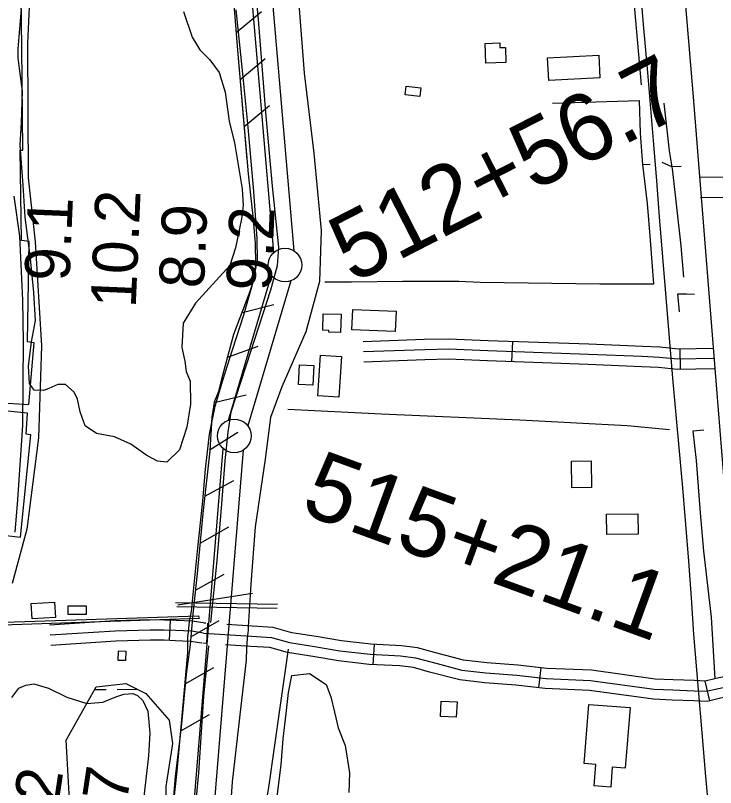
# Model space of a CAD drawing. Extents: x 3715084 to 3753216, y 488173 to 513963.
# Drawn here: x 3735343 to 3736383, y 503889 to 505035 of the extents above; entities that cross this region are included whole.
import ezdxf

# ---------------------------------------------------------------- set-up
doc = ezdxf.new("R2010")
doc.units = 0
for name, color, linetype in [('V-BLDG-OTLN', 7, 'Continuous'), ('V-CHAN-DOCK', 7, 'Continuous'), ('V-FLOD-BASE', 7, 'Continuous'), ('V-LEVE-TOET', 7, 'Continuous'), ('V-RAIL-TRAK', 7, 'Continuous'), ('V-RIVR-EDGE', 7, 'Continuous'), ('V-RIVR-RANG', 7, 'Continuous'), ('V-ROAD-CNTR', 7, 'Continuous'), ('V-RRAP-FSHR', 7, 'Continuous'), ('V-RRAP-RVMT', 7, 'Continuous'), ('V-SITE-VEGE', 7, 'Continuous'), ('V-SURV-IDEN', 7, 'Continuous'), ('V-SURV-LINE', 7, 'Continuous'), ('V-TOPO-SHOR', 7, 'Continuous'), ('V-UTIL-LINE', 7, 'Continuous'), ('V-WETL-SWMP', 7, 'Continuous')]:
    doc.layers.add(name, color=color, linetype=linetype)

msp = doc.modelspace()

# ---------------------------------------------------------------- linework, layer by layer
at = {"layer": 'V-BLDG-OTLN'}
for points in [[(3736040.8, 504993.8), (3736062.7, 504994.4), (3736062.9, 504987.4), (3736071.1, 504987.6), (3736071.7, 504965.5), (3736041.7, 504964.6)], [(3736211.3, 504942.4), (3736135.3, 504938.5), (3736133.6, 504972.2), (3736209.6, 504976)], [(3735923.6, 504930.1), (3735945.5, 504927.5), (3735944, 504914.9), (3735922.1, 504917.5)], [(3735844.1, 504598.6), (3735908.5, 504596), (3735907.3, 504566), (3735842.9, 504568.6)], [(3735800.3, 504592.2), (3735826.7, 504591.6), (3735826, 504564.5), (3735808.7, 504564.9), (3735808.8, 504567.7), (3735799.7, 504568)], [(3735827.3, 504529.1), (3735823.4, 504468.6), (3735792.4, 504470.6), (3735796.3, 504531.1)], [(3735786.3, 504515.5), (3735785, 504486.5), (3735763.5, 504487.5), (3735764.8, 504516.4)], [(3736169.8, 504333.9), (3736169.2, 504373.6), (3736198.5, 504374), (3736199.1, 504334.3)], [(3736221.1, 504294.7), (3736267.9, 504295.4), (3736268.3, 504265.3), (3736221.5, 504264.7)], [(3735366.4, 504162.1), (3735401.1, 504164), (3735402.4, 504141.2), (3735367.6, 504139.3)], [(3735421.1, 504158.9), (3735448.1, 504158.9), (3735448.1, 504146), (3735421.1, 504146)], [(3735506.9, 504091.6), (3735506.5, 504077.4), (3735495.8, 504077.7), (3735496.2, 504091.8)], [(3735975.5, 504017.4), (3735999.3, 504016.1), (3735998, 503993.4), (3735974.3, 503994.7)], [(3736256.2, 504007.6), (3736249.1, 503917.9), (3736229.8, 503919.5), (3736227.4, 503889.6), (3736202.9, 503891.6), (3736205.4, 503923.4), (3736187.8, 503924.8), (3736194.8, 504012.5)]]:
    msp.add_lwpolyline(points, close=True, dxfattribs=at)
at = {"layer": 'V-CHAN-DOCK'}
msp.add_lwpolyline([(3735615.8, 504139.9), (3735308.3, 504129.4), (3735299.2, 504129.4), (3735298.8, 504119.5), (3735269.6, 504121.9), (3735275.5, 504232), (3735304.3, 504229.6), (3735299.2, 504133.7), (3735310.6, 504134.1), (3735615, 504143.9), (3735615.8, 504139.9)], dxfattribs=at)
at = {"layer": 'V-FLOD-BASE'}
for points in [[(3735687.3, 505204.1), (3735703.7, 505029), (3735714.4, 504891.2), (3735724.4, 504781.8), (3735733.9, 504691.4), (3735732, 504663.6), (3735721.9, 504627.6), (3735692.1, 504535.9), (3735663, 504446.2), (3735658.6, 504416.5), (3735654.1, 504374.1), (3735649.1, 504310.3), (3735642.1, 504226.2), (3735632.6, 504134)], [(3735630, 504099.2), (3735622.4, 504024), (3735614.8, 503910.8), (3735604.6, 503800.8)]]:
    msp.add_lwpolyline(points, dxfattribs=at)
at = {"layer": 'V-LEVE-TOET'}
for points in [[(3735763.8, 505051.9), (3735771.9, 504949.4), (3735786.2, 504830.7), (3735797.4, 504715.8), (3735794.9, 504640.2), (3735774.2, 504565.3), (3735738.6, 504484.1), (3735721.7, 504438.5), (3735714.2, 504376.6), (3735699.2, 504276), (3735692.9, 504191.1), (3735688.5, 504127.4), (3735688.5, 504122.4), (3735687.7, 504114.6)], [(3735573.8, 503827.2), (3735583.2, 503913.4), (3735591.4, 504000.8), (3735598.9, 504089.5), (3735598.9, 504102.7), (3735598.9, 504113.3), (3735600.2, 504120.4), (3735601.4, 504135.4), (3735604.6, 504151), (3735613.3, 504239.7), (3735621.5, 504314.7), (3735625.2, 504361.5), (3735631.5, 504413.4), (3735639.6, 504455.2), (3735650.9, 504493.9), (3735665.3, 504538.9), (3735682.2, 504590.8), (3735695.3, 504635.7), (3735702.8, 504671.3), (3735702.2, 504703.8), (3735697.2, 504773.8), (3735688.5, 504869.4), (3735680.4, 504953.7), (3735671.1, 505043.7)], [(3735687.7, 504114.6), (3735687.2, 504110), (3735686.5, 504096.2), (3735685.9, 504078.1), (3735677.7, 504010), (3735665.2, 503897.6), (3735656.4, 503775.7)]]:
    msp.add_lwpolyline(points, dxfattribs=at)
at = {"layer": 'V-RAIL-TRAK'}
msp.add_lwpolyline([(3736270.5, 505081.8), (3736276.1, 505016.2), (3736281.9, 504950.6), (3736286.7, 504897.1), (3736291.2, 504843.5), (3736295.5, 504789.9), (3736299.5, 504736.3), (3736319, 504496.8), (3736324.3, 504442.5), (3736329.3, 504388.2), (3736334.1, 504333.8), (3736338.5, 504279.5), (3736342.8, 504225.1), (3736346.8, 504170.7), (3736350.5, 504116.3), (3736357.4, 504034.8), (3736362.9, 503970.1), (3736368.5, 503905.4), (3736374.4, 503840.8)], dxfattribs=at)
at = {"layer": 'V-RIVR-EDGE'}
msp.add_lwpolyline([(3735342.6, 504268.1), (3735346.4, 504316.1), (3735353.8, 504427.1), (3735354.7, 504550.8), (3735353.7, 504612.6), (3735349.7, 504707.5), (3735340.9, 504766.9)], dxfattribs=at)
at = {"layer": 'V-ROAD-CNTR'}
for p, q in [((3736080.7, 504521), (3736081.8, 504551)), ((3736331.2, 504509.9), (3736330.7, 504539.9)), ((3735572.1, 504107.3), (3735573.3, 504137.3)), ((3735627.1, 504102.8), (3735629, 504132.8)), ((3735874.7, 504071.6), (3735876.3, 504101.6)), ((3736120.6, 504037), (3736124, 504066.8)), ((3736374.6, 504017.8), (3736367.8, 504047))]:
    msp.add_line(p, q, dxfattribs=at)
for points in [[(3736184.7, 506906.1), (3736197, 506766.8), (3736212.8, 506567.9), (3736232.6, 506284.2), (3736257.8, 505993.5), (3736279.1, 505753.5), (3736349.3, 504920.1), (3736384.6, 504480.2), (3736421.9, 504020), (3736483.8, 503285.7), (3736534.1, 502641.5), (3736554.4, 502400)], [(3736734.3, 504774.5), (3736720.8, 504779.1), (3736701.3, 504784.1), (3736677.6, 504788.1), (3736647.5, 504791.7), (3736621.8, 504794.9), (3736589.9, 504795.2), (3736522.6, 504795.5), (3736360.5, 504794.4)], [(3737959.8, 504703.9), (3736892.8, 504713.3), (3736874.3, 504714.1), (3736854.9, 504714.9), (3736834.5, 504716.9), (3736811.2, 504720.9), (3736784.4, 504727.6), (3736756.5, 504735.4), (3736737.4, 504741.8), (3736712.3, 504750.3), (3736695.1, 504754.7), (3736673.3, 504758.4), (3736643.8, 504761.9), (3736619.8, 504765), (3736589.7, 504765.2), (3736522.6, 504765.5), (3736360.7, 504764.4)], [(3736380.7, 504540.8), (3736328, 504539.9), (3736300.6, 504542.6), (3736275, 504543.6), (3736194.8, 504547), (3736045.5, 504552.3), (3735986.6, 504554.7), (3735950.5, 504553.9), (3735859.4, 504550.7)], [(3736381, 504525.8), (3736327.4, 504524.9), (3736299.6, 504527.6), (3736274.4, 504528.7), (3736194.3, 504532), (3736044.9, 504537.3), (3735986.4, 504539.7), (3735951, 504538.9), (3735859.9, 504535.7)], [(3736381.2, 504510.8), (3736326.7, 504509.8), (3736298.5, 504512.6), (3736273.7, 504513.7), (3736193.7, 504517), (3736044.4, 504522.3), (3735986.3, 504524.7), (3735951.4, 504523.9), (3735860.4, 504520.7)], [(3735624.8, 504133), (3735606.1, 504135.9), (3735581.6, 504137), (3735564.4, 504137.7), (3735543, 504137.8), (3735490.6, 504136.3), (3735393.4, 504130)], [(3735625.7, 504133), (3735623.4, 504133.1)], [(3736416.9, 504057.9), (3736384.3, 504050.8), (3736368, 504047.1), (3736352, 504047.8), (3736320, 504048.8), (3736293.5, 504050), (3736198.7, 504063.1), (3736132.5, 504065.9), (3736089.2, 504070.8), (3736043.2, 504074.3), (3736008.8, 504078.2), (3735965.8, 504089.4), (3735940.4, 504096.5), (3735916.5, 504099.4), (3735871.2, 504101.8), (3735827.2, 504107), (3735789.7, 504113.3), (3735753.5, 504118.9), (3735725.8, 504126.7), (3735694.6, 504128.6), (3735657, 504131)], [(3735622.5, 504118.2), (3735604.6, 504121), (3735580.9, 504122), (3735564, 504122.7), (3735543.2, 504122.8), (3735491.3, 504121.3), (3735394.4, 504115)], [(3735622.5, 504118.2), (3735693.7, 504113.6), (3735723.3, 504111.8), (3735750.3, 504104.2), (3735787.3, 504098.4), (3735825.1, 504092.2), (3735869.9, 504086.9), (3735915.2, 504084.5), (3735937.5, 504081.7), (3735961.9, 504074.9), (3736006, 504063.5), (3736041.8, 504059.3), (3736087.7, 504055.8), (3736131.3, 504050.9), (3736197.4, 504048.1), (3736292.1, 504035), (3736319.5, 504033.9), (3736351.5, 504032.8), (3736369.4, 504032), (3736387.6, 504036.2), (3736420, 504043.2)], [(3735620.1, 504103.3), (3735603.1, 504106), (3735580.3, 504107), (3735563.7, 504107.7), (3735543.4, 504107.8), (3735492, 504106.3), (3735395.4, 504100)], [(3735628, 504102.8), (3735621.5, 504103.2)], [(3736423.2, 504028.5), (3736390.8, 504021.6), (3736370.8, 504016.9), (3736350.9, 504017.8), (3736318.9, 504018.9), (3736290.8, 504020), (3736196, 504033.2), (3736130.1, 504035.9), (3736086.3, 504040.9), (3736040.3, 504044.4), (3736003.2, 504048.7), (3735958, 504060.5), (3735934.5, 504067), (3735913.9, 504069.5), (3735868.7, 504071.9), (3735823, 504077.3), (3735784.9, 504083.6), (3735747.1, 504089.5), (3735720.8, 504096.9), (3735692.7, 504098.6), (3735655, 504101)]]:
    msp.add_lwpolyline(points, dxfattribs=at)
at = {"layer": 'V-RRAP-FSHR'}
for p, q in [((3735670.7, 505009.8), (3735708.4, 505040.9)), ((3735676.7, 504940.1), (3735714.1, 504971.4)), ((3735682.7, 504870.3), (3735720.2, 504901.7)), ((3735679.6, 504594.2), (3735727, 504606.1)), ((3735657.9, 504527.8), (3735703.8, 504544.2)), ((3735638.2, 504460.7), (3735685.7, 504472.2)), ((3735632.1, 504391), (3735673.6, 504416.7)), ((3735624.4, 504321.4), (3735667.3, 504344.8)), ((3735617.2, 504251.8), (3735659.8, 504275.8)), ((3735610.3, 504182.2), (3735653, 504205.9)), ((3735603.7, 504112.5), (3735645.9, 504136.9)), ((3735595.3, 504043), (3735637.7, 504067.2)), ((3735588.9, 503973.3), (3735631.3, 503997.5))]:
    msp.add_line(p, q, dxfattribs=at)
for points in [[(3735342.7, 505718.1), (3735359.4, 505430.2), (3735361.2, 505309.9), (3735366.7, 505124.6), (3735360.7, 504993.5), (3735361.9, 504794.3), (3735372.3, 504699), (3735381.8, 504544.8), (3735377, 504408), (3735359.9, 504272.7), (3735338.2, 504191.8)], [(3735634.5, 505434.6), (3735638.8, 505392.9), (3735646, 505297.8), (3735652.3, 505211.8), (3735661.4, 505126.3), (3735672.3, 504989.6), (3735687, 504821.5)], [(3735661.4, 505126.3), (3735672.3, 504989.6), (3735688.9, 504800), (3735695.9, 504737.4), (3735699.1, 504697.2), (3735699.4, 504666.1), (3735696.5, 504641.3), (3735689.9, 504621.2), (3735667.1, 504561.5), (3735648.9, 504495.3), (3735644.5, 504476.7), (3735638.4, 504461.1), (3735634.8, 504438.8), (3735632, 504388.7), (3735621.5, 504295.6), (3735612.8, 504206.8), (3735606.7, 504146.9)], [(3735685.4, 504609.5), (3735667.1, 504561.5), (3735648.9, 504495.3), (3735644.5, 504476.7), (3735638.4, 504461.1), (3735634.8, 504438.8), (3735632, 504388.7), (3735621.5, 504295.6), (3735612.8, 504206.8), (3735606.7, 504146.9), (3735602.6, 504100.7), (3735596.7, 504057.5), (3735589.4, 503978.8), (3735586.9, 503958.1)], [(3735602.6, 504100.7), (3735596.7, 504057.5), (3735589.4, 503978.8), (3735580.3, 503905.2), (3735573, 503817.2), (3735565.8, 503745.6), (3735560.3, 503702.1), (3735556.6, 503655.9), (3735559.9, 503616.7), (3735566, 503570.3), (3735588.7, 503447.1), (3735620.8, 503287.1), (3735621.7, 503265.7), (3735619, 503227), (3735567.3, 503044.5), (3735505.9, 502792.8), (3735359.9, 502232.6), (3735347.3, 502162.3), (3735339.2, 502137.8)]]:
    msp.add_lwpolyline(points, dxfattribs=at)
at = {"layer": 'V-RRAP-RVMT'}
for p, q in [((3735352.5, 504987.6), (3735350.2, 505125.5)), ((3735353.7, 504835.2), (3735352.5, 504987.6)), ((3735350, 504835), (3735353.7, 504835.2)), ((3735352.2, 504700.9), (3735350, 504835)), ((3735363.2, 504699.7), (3735352.2, 504700.9)), ((3735360.9, 504550.7), (3735363.2, 504699.7)), ((3735370.9, 504549.2), (3735360.9, 504550.7)), ((3735362.7, 504457.7), (3735370.9, 504549.2)), ((3735314.9, 504460.6), (3735362.7, 504457.7)), ((3735360.7, 504444.7), (3735314.3, 504449.5)), ((3735358.7, 504413.5), (3735360.7, 504444.7)), ((3735350.7, 504260.8), (3735366, 504412.6)), ((3735366, 504412.6), (3735358.7, 504413.5)), ((3735273.4, 504269), (3735350.7, 504260.8))]:
    msp.add_line(p, q, dxfattribs=at)
at = {"layer": 'V-SITE-VEGE'}
for points in [[(3735592.8, 505041), (3735605.4, 505003.1), (3735616.8, 504984.1), (3735632, 504969.5), (3735645.9, 504950.6), (3735654.7, 504921.5), (3735660.4, 504878.5), (3735668.6, 504846.3), (3735679.9, 504778), (3735681.2, 504753.3), (3735678.7, 504733.1), (3735669.8, 504690.1), (3735661.6, 504664.2), (3735610.3, 504608), (3735592, 504578.3), (3735590.1, 504542.2), (3735594.5, 504522), (3735596.4, 504506.8), (3735602.7, 504492.3), (3735603.3, 504458.2), (3735597.6, 504424), (3735586.9, 504390.5), (3735567.9, 504372.2), (3735554, 504373.5), (3735538.2, 504381.7), (3735514.2, 504398.8), (3735490.2, 504409.5), (3735463.6, 504414.6), (3735446.6, 504426), (3735439, 504446.9), (3735435.2, 504465.8), (3735430.1, 504475.9), (3735417.5, 504487.3), (3735406.1, 504487.3), (3735392.8, 504481.6), (3735384.6, 504478.5), (3735370.7, 504479.1), (3735363.8, 504488.6), (3735362.5, 504514.5), (3735367, 504550.5), (3735372.7, 504582.1), (3735370.1, 504623.9), (3735365.1, 504674.4), (3735357.5, 504735.8), (3735354.4, 504783.2), (3735350, 504842.6), (3735351.9, 504876.1), (3735353.2, 504922.9), (3735348.8, 504956.4), (3735346.9, 504972.2), (3735346.9, 504985.4), (3735352, 505044.9)], [(3735728.9, 503852), (3735737.8, 503922.7), (3735740.6, 503961.2), (3735745.4, 503999), (3735748.9, 504029.9), (3735753.7, 504055.3), (3735779.8, 504058.1), (3735804.5, 504042.2), (3735811.4, 504023.7), (3735816.9, 504001), (3735822.4, 503977.7), (3735832.7, 503951.6), (3735839.5, 503911), (3735838.1, 503881.5)], [(3735337.8, 504022.7), (3735348, 504036.7), (3735358.2, 504041.2), (3735370.3, 504043.1), (3735392, 504036.7), (3735419.3, 504023.3), (3735449.2, 504013.8), (3735472.8, 504015.7), (3735491.9, 504023.9), (3735504, 504027.7), (3735517.4, 504028.4), (3735524.4, 504025.8), (3735532, 504018.2), (3735539.6, 504002.3), (3735542.8, 503969.8), (3735540.9, 503936.1), (3735532.6, 503866.7)]]:
    msp.add_lwpolyline(points, dxfattribs=at)
at = {"layer": 'V-SURV-LINE'}
for points in [[(3735679.8, 505580.6), (3735756.7, 504685.8)], [(3735726.8, 504683.2), (3735649.9, 505578)], [(3735659.4, 504434.6), (3735723.4, 504649.7)], [(3735752.1, 504641.1), (3735688.1, 504426)], [(3735592, 503666.8), (3735651.5, 504392.5)], [(3735681.4, 504390), (3735621.9, 503664.3)]]:
    msp.add_lwpolyline(points, dxfattribs=at)
for centre in [(3735743.4, 504664.6), (3735668.1, 504411.1)]:
    msp.add_circle(centre, 25, dxfattribs=at)
at = {"layer": 'V-TOPO-SHOR'}
for points in [[(3736273.1, 504932.2), (3736263.5, 505044.3), (3736252, 505191.1), (3736236.1, 505350), (3736221.4, 505514.7), (3736215, 505594.8)], [(3736140.7, 504905.1), (3736269.9, 504909.1), (3736271.2, 504860.4), (3736274.6, 504813.7), (3736286.3, 504814.4)], [(3736306.3, 504905), (3736314.5, 504834.3), (3736318.2, 504810.3), (3736319.3, 504803.3), (3736331.6, 504693.4), (3736335.7, 504646.7)], [(3736274.6, 504813.7), (3736281.5, 504756), (3736286.3, 504701.7), (3736291.1, 504636.4), (3736211.4, 504636.4), (3736033.4, 504638.6), (3736001.8, 504640), (3735918, 504640), (3735842.5, 504639.3), (3735802.6, 504639.3)], [(3736332.1, 504811), (3736318.2, 504810.3), (3736304.1, 504816.7)], [(3736329.7, 504595), (3736327.1, 504621.9), (3736339.9, 504621.9), (3736352.1, 504621.3)], [(3736314.9, 504420.1), (3736252.1, 504425.9), (3736092.5, 504434.3), (3735886.8, 504443.3), (3735747.7, 504450.4)], [(3736365.9, 504419.3), (3736349.4, 504417.9), (3736354.2, 504374.7), (3736360.3, 504297), (3736365.1, 504240), (3736376.7, 504141.8), (3736382.2, 504050.4)], [(3735748.1, 504094.6), (3735735.7, 504008), (3735719.2, 503889.2), (3735702, 503793), (3735683.4, 503678.3), (3735680.6, 503618.5), (3735686.1, 503534.7), (3735696.4, 503465.3), (3735707.3, 503389.1), (3735719, 503306.6), (3735722.4, 503270.9), (3735718.3, 503230.4), (3735709.3, 503165.1), (3735690.1, 503087.5), (3735653.6, 502956.3), (3735615.1, 502808.6), (3735571, 502641), (3735545.6, 502544.1), (3735505.7, 502392.3), (3735470.6, 502262.5), (3735450, 502180.7), (3735446.5, 502138.8), (3735455.4, 502096.2), (3735469.2, 502070.8)]]:
    msp.add_lwpolyline(points, dxfattribs=at)
at = {"layer": 'V-UTIL-LINE'}
for p, q in [((3735584.4, 504160.4), (3735695.3, 504177.4)), ((3735580.9, 504163.7), (3735732.3, 504161.1)), ((3735582.9, 504157.8), (3735731.7, 504155.2))]:
    msp.add_line(p, q, dxfattribs=at)
at = {"layer": 'V-WETL-SWMP'}
for p, q in [((3735460.4, 504034.4), (3735477.9, 504034.6)), ((3735493.9, 504034.8), (3735523.8, 504035.2))]:
    msp.add_line(p, q, dxfattribs=at)
msp.add_lwpolyline([(3735423.2, 503870.6), (3735418.2, 503959.5), (3735462.7, 504038.6), (3735507.2, 504043.5), (3735536.8, 504028.7), (3735571.4, 503989.2), (3735576.3, 503954.6), (3735566.4, 503890.4), (3735566.4, 503831.1)], dxfattribs=at)

# ---------------------------------------------------------------- texts
at = {"layer": 'V-RIVR-RANG'}
for s, rotation, p in [('10.2', 87.5783, (3735521.6, 504600.2)), ('9.1', 87.5783, (3735423.2, 504639.8)), ('8.9', 87.5783, (3735622.9, 504629.2)), ('9.2', 87.5783, (3735722.9, 504625.5)), ('10.7', 81.4283, (3735489.6, 503741.6)), ('9.2', 81.4283, (3735395.6, 503789.1))]:
    msp.add_text(s, height=67, rotation=rotation, dxfattribs=at).set_placement(p)
at = {"layer": 'V-SURV-IDEN'}
for s, rotation, p in [('512+56.7', 27.079, (3735844, 504636.4)), ('515+21.1', 340.0052, (3735764, 504297.5))]:
    msp.add_text(s, height=100, rotation=rotation, dxfattribs=at).set_placement(p)

doc.saveas('drawing.dxf')
